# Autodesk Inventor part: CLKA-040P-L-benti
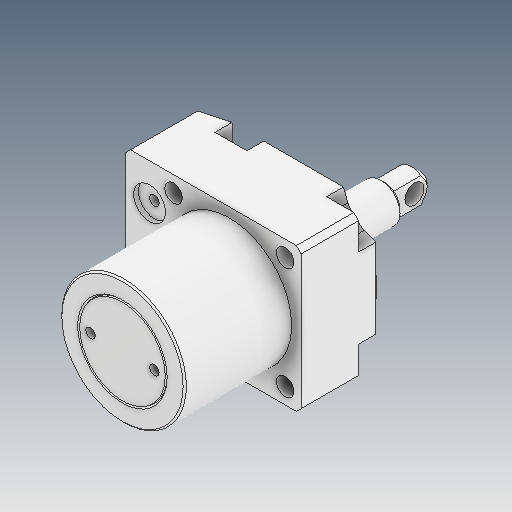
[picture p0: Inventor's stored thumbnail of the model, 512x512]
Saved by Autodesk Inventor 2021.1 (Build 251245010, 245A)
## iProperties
Created: 2021-06
Part Number: CLKA-040P-L-benti
Material: Ogólny
Document SubType Name: Modeling
Designer: user
Density: 1 g/cm^3
Appearance: Domyślna
Author: user
Revision Number: ÈÎºÎ
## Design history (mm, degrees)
feature "Í¹Ì¨-À­Éì4"
node "Bryła1"
